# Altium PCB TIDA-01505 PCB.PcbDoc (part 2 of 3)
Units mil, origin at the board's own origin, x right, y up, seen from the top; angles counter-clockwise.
Board outline 7874.02 x 6929.13 mil, 2 copper layers (Top Layer, Bottom Layer), stack 62 mil thick; 307 components, 129 nets, 623 pads, 701 vias.
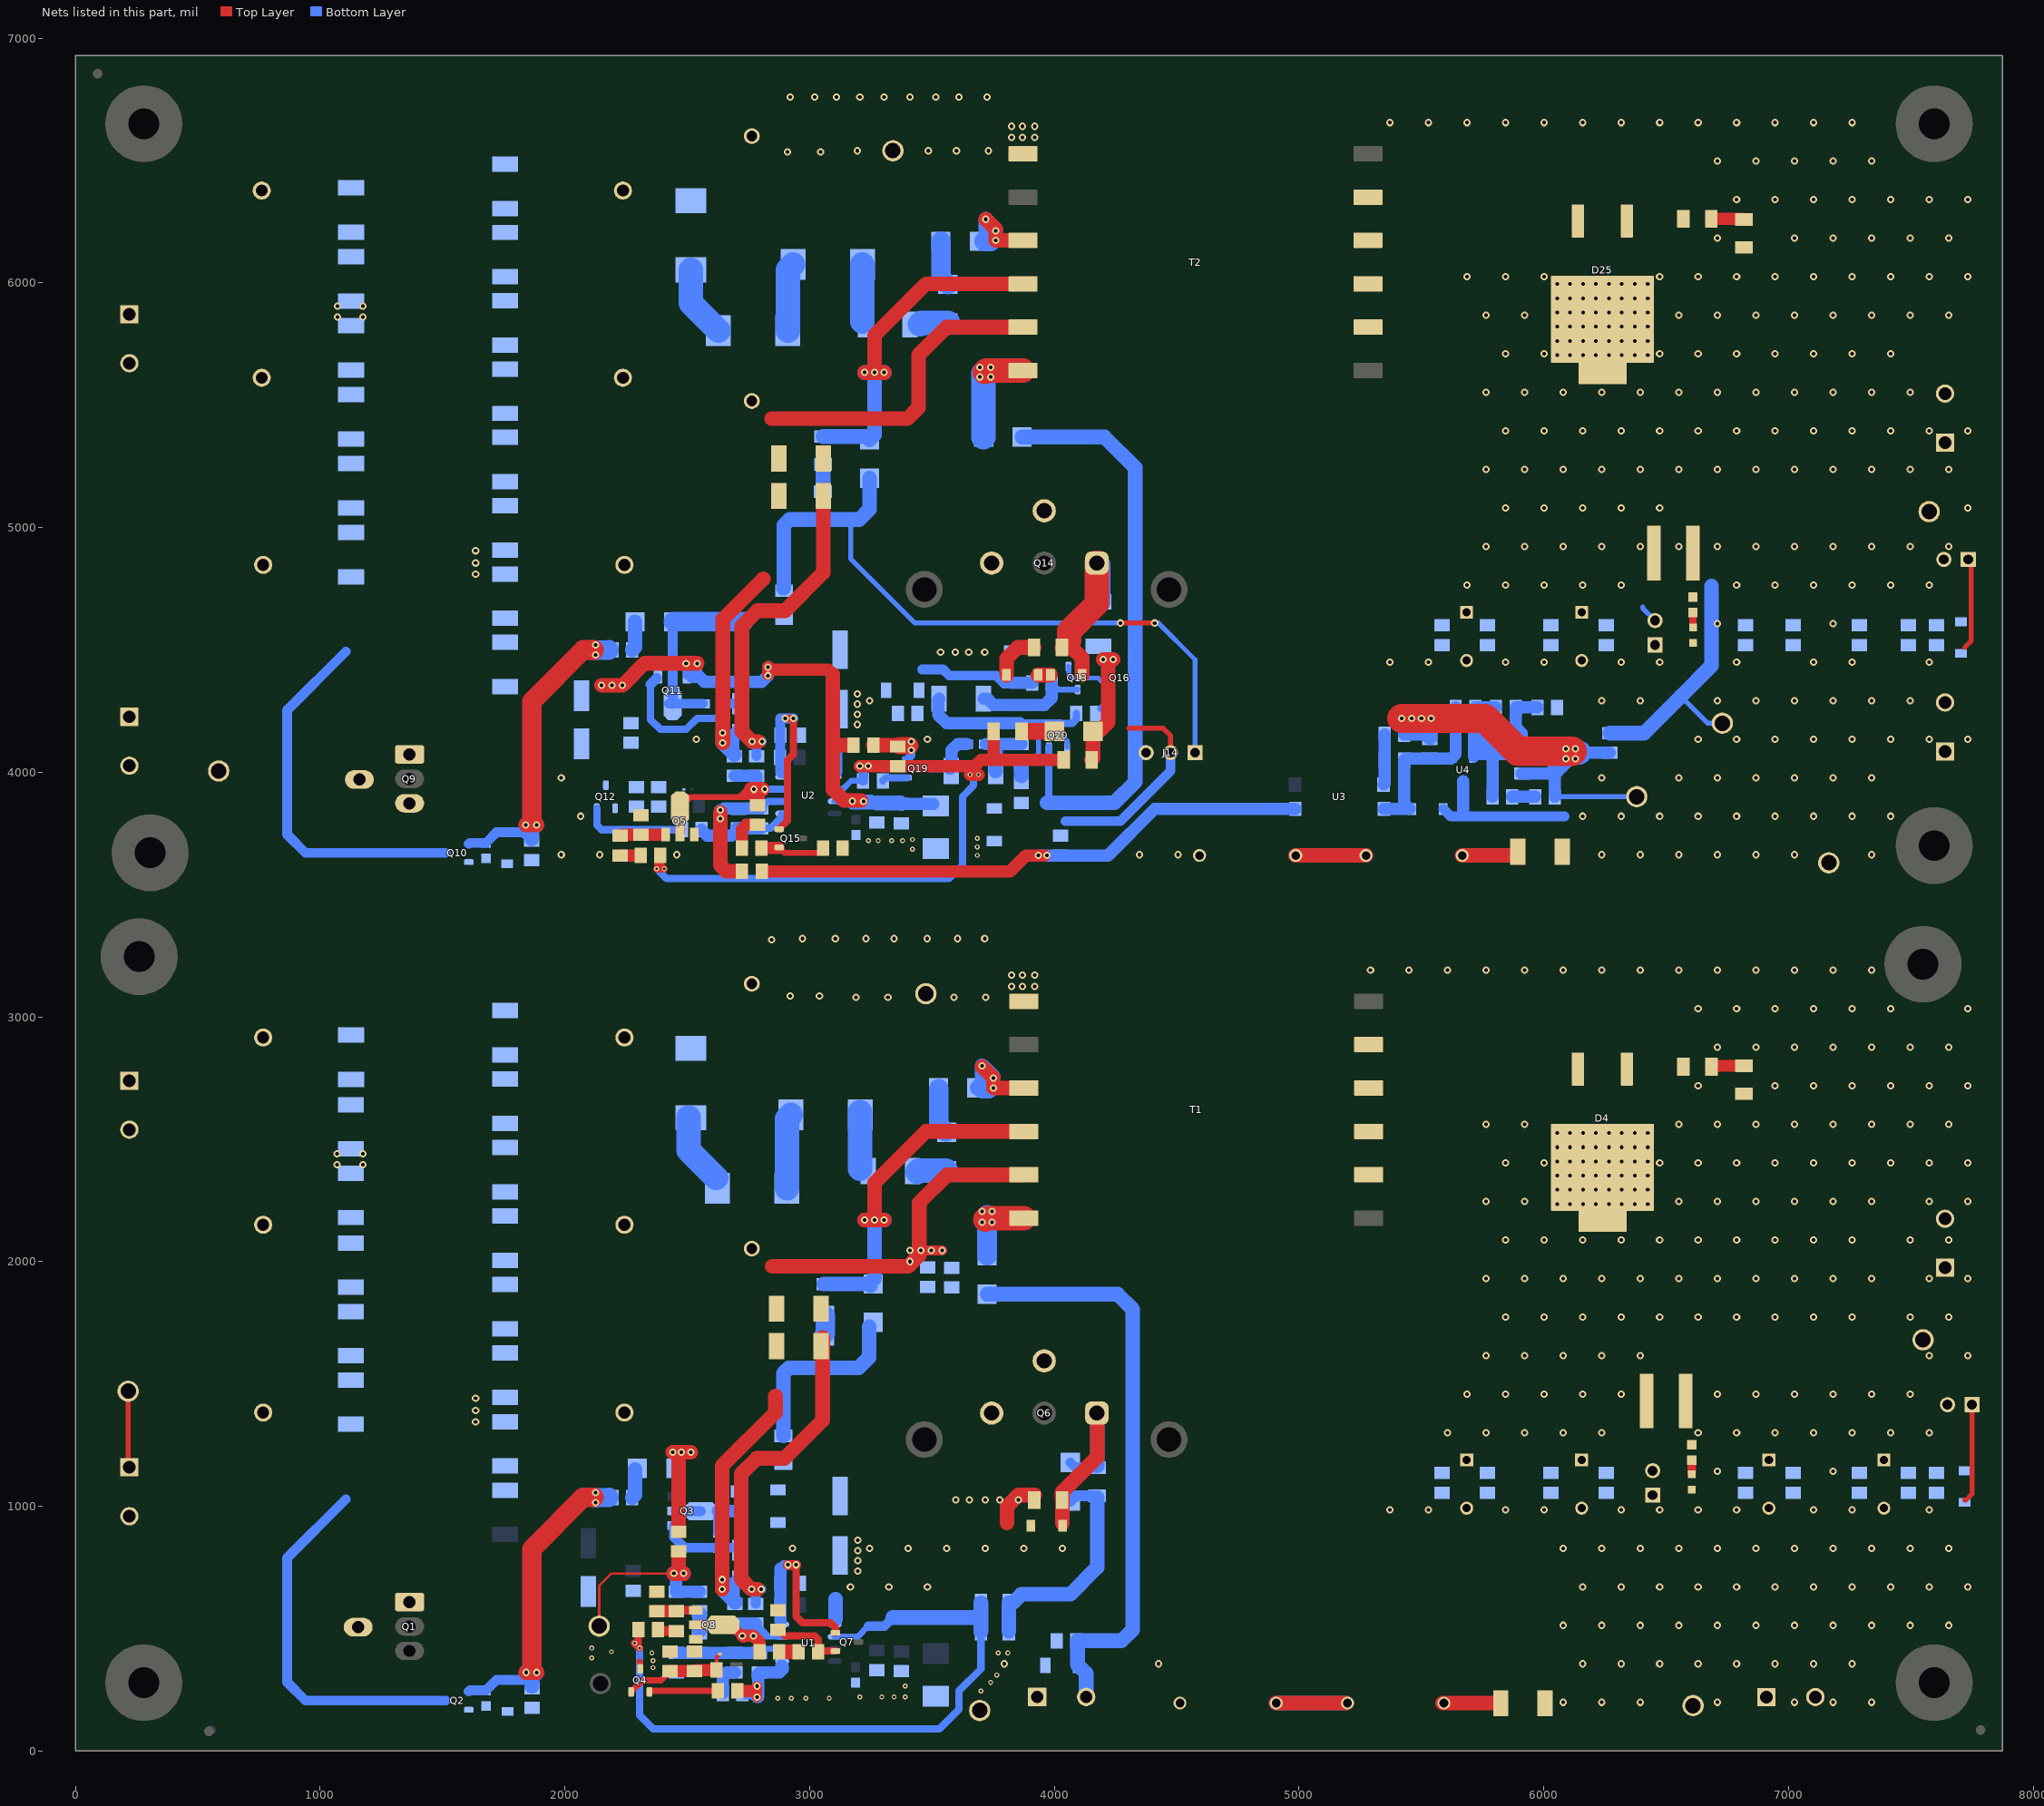
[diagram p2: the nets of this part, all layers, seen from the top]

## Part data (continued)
Q2 Q10: "MOSFET, N-CH, 60 V, 0.17 A, SOT-23", Alternate Manufacturer=None, Manufacturer="Diodes Inc.", Supplier Part Number 1=2N7002-FDICT-ND, Value1="7.5 ohm", Value2="223 nC"
Q3 Q11: library part "PBSS4250X,115, Nexperia", "Transistor, NPN, 50 V, 2 A, SOT-89", Manufacturer=Nexperia, Supplier Part Number 1=568-7297-1-ND, Value1="2 A"
Q4 Q12: library part "MMBT2907ALT1G, ON Semiconductor", "Transistor, PNP, 60 V, 0.6 A, SOT-23", Manufacturer="ON Semiconductor", Supplier Part Number 1=MMBT2907ALT1GOSCT-ND, Value1="0.6 A"
Q5 Q8: library part "DXT2222A-13, Diodes Inc.", "Transistor, NPN, 40 V, 0.6 A, SOT-89", Manufacturer="Diodes Inc.", Supplier Part Number 1=DXT2222ADITR-ND, Value1="0.6 A", Value2=300
Q6 Q14: "MOSFET, N-CH, 1700 V, 5 A, TO-247", Alternate Manufacturer=None, Manufacturer=Cree, Supplier Part Number 1=C2M1000170D-ND, Value1="? ohm", Value2="13 nC"
Q7 Q15: library part "MMBT3904-7-F, Diodes Inc.", "Transistor, NPN, 40 V, 0.2 A, SOT-23", Manufacturer="Diodes Inc.", Supplier Part Number 1=MMBT3904-FDICT-ND, Value1="0.2 A", Value2=400
Q13: library part "BC817-16LT1G, ON Semiconductor", "Transistor, NPN, 45 V, 0.5 A, SOT-23", Manufacturer="ON Semiconductor", Supplier Part Number 1=BC817-16LT1GOSCT-ND, Value1="0.5 A", Value2=250
Q16: library part "BC807-40LT1G, ON Semiconductor", "Transistor, PNP, 45 V, 0.5 A, AEC-Q101, SOT-23", Manufacturer="ON Semiconductor", Supplier Part Number 1=BC807-40LT1GOSCT-ND, Value1="0.5 A", Value2=600
Q19: "MOSFET, P-CH, -50 V, -0.13 A, SOT-23", Alternate Manufacturer=None, Manufacturer="Diodes Inc.", Supplier Part Number 1=BSS84-FDICT-ND, Value1="? ohm", Value2="? nC"
Q20: "MOSFET, N-CH, 60 V, 0.3 A, SOT-23", Alternate Manufacturer=None, Manufacturer=Vishay-Siliconix, Supplier Part Number 1=2N7002K-T1-E3CT-ND, Value1="4 ohm", Value2="0.4 nC"
R1 R36: library part CMP-0016044-2, "RES, 0, 5%, 0.75 W, AEC-Q200 Grade 0, 2010", Manufacturer=Vishay-Dale, Power_W=750mW, Supplier Part Number 1=541-0.0WCT-ND, TempCo=ppm/C, Tolerance_%=5%, Value2=0.75W, Value_Code=0000, ValueDisplayed=0
R2 R4 R6 R9 R14 R15 R37 R39 R41 R44 R48 R49: library part CMP-0077778-1, "RES, 1.5 M, 5%, 0.75 W, AEC-Q200 Grade 0, 2010", Manufacturer=Panasonic, Power_W=750mW, Supplier Part Number 1=P1.5MWCT-ND, Tolerance_%=5%, Value2=0.75W, Value_Code=1M50, ValueDisplayed=1.5M
R3 R5 R7 R8 R10 R11 R38 R40 R42 R43 R45 R46: "RES, 49.9 k, 1%, 0.75 W, AEC-Q200 Grade 0, 2010", Manufacturer=Vishay-Dale, Power_W=0.75, Supplier Part Number 1=541-49.9KACCT-ND, TempCo="100 ppm/C", Tolerance_%=1, Value1=1%, Value2=0.75W, Value_Code=49k9, ValueDisplayed=49.9k
R12 R47: "RES, 33, 5%, 0.75 W, AEC-Q200 Grade 0, 2010", Manufacturer=Vishay-Dale, Power_W=0.75, Supplier Part Number 1=541-33.0WCT-ND, TempCo="200 ppm/C", Tolerance_%=5, Value1=5%, Value2=0.75W, Value_Code=33R0, ValueDisplayed=33
R13 R16 R50 R51: "RES, 1.00 M, 1%, 0.75 W, AEC-Q200 Grade 0, 2010", Manufacturer=Vishay-Dale, Power_W=0.75, Supplier Part Number 1=541-1.0MACCT-ND, TempCo="100 ppm/C", Tolerance_%=1, Value1=1%, Value2=0.75W, Value_Code=1M00, ValueDisplayed=1.00M
R17 R52 R61: "RES, 2.00 k, 1%, 0.125 W, 0805", Manufacturer=Vishay-Dale, Power_W=0.125, Supplier Part Number 1=541-2.00KCCT-ND, TempCo="100 ppm/C", Tolerance_%=1, Value1=1%, Value2=0.125W, Value_Code=2k00, ValueDisplayed=2.00k
R18: "RES, 10.0, 1%, 0.125 W, 0805", Manufacturer=Vishay-Dale, Power_W=0.125, Supplier Part Number 1=541-10.0CCT-ND, TempCo="100 ppm/C", Tolerance_%=1, Value1=1%, Value2=0.125W, Value_Code=10R0, ValueDisplayed=10.0
R19 R54: "RES, 499 k, 1%, 0.1 W, 0603", Manufacturer=Vishay-Dale, Power_W=0.1, Supplier Part Number 1=541-499KHCT-ND, TempCo="100 ppm/C", Tolerance_%=1, Value1=1%, Value2=0.1W, Value_Code=499k
R20 R55: "RES, 4.7 k, 5%, 0.1 W, 0603", Manufacturer=Vishay-Dale, Power_W=0.1, Supplier Part Number 1=541-4.7KGCT-ND, TempCo="200 ppm/C", Tolerance_%=5, Value1=5%, Value2=0.1W, Value_Code=4k70, ValueDisplayed=4.7k
R21 R56: library part CMP-0021998-2, "RES, 10.0 k, 1%, 0.1 W, 0603", Manufacturer=Vishay-Dale, Power_W=100mW, Supplier Part Number 1=541-10.0KHCT-ND, TempCo="100 ppm/C", Tolerance_%=1%, Value2=0.1W, Value_Code=10k0, ValueDisplayed=10.0k
R22 R57: "RES, 20.0 k, 1%, 0.125 W, 0805", Manufacturer=Vishay-Dale, Power_W=0.125, Supplier Part Number 1=541-20.0KCCT-ND, TempCo="100 ppm/C", Tolerance_%=1, Value1=1%, Value2=0.125W, Value_Code=20k0, ValueDisplayed=20.0k
R23 R64: "RES, 49.9, 1%, 0.125 W, 0805", Manufacturer=Vishay-Dale, Power_W=0.125, Supplier Part Number 1=541-49.9CCT-ND, TempCo="100 ppm/C", Tolerance_%=1, Value1=1%, Value2=0.125W, Value_Code=49R9, ValueDisplayed=49.9
R24 R25 R27 R53 R80 R95: "RES, 10.0, 1%, 0.25 W, 1206", Manufacturer=Vishay-Dale, Power_W=0.25, Supplier Part Number 1=541-10.0FCT-ND, TempCo="100 ppm/C", Tolerance_%=1, Value1=1%, Value2=0.25W, Value_Code=10R0, ValueDisplayed=10.0
R26 R60: "RES, 13.0 k, 1%, 0.125 W, 0805", Manufacturer=Vishay-Dale, Power_W=0.125, Supplier Part Number 1=541-13.0KCCT-ND, TempCo="100 ppm/C", Tolerance_%=1, Value1=1%, Value2=0.125W, Value_Code=13k0, ValueDisplayed=13.0k
R28 R30: "RES, 20.5 k, 1%, 0.125 W, 0805", Manufacturer=Vishay-Dale, Power_W=0.125, Supplier Part Number 1=541-20.5KCCT-ND, TempCo="100 ppm/C", Tolerance_%=1, Value1=1%, Value2=0.125W, Value_Code=20k5, ValueDisplayed=20.5k
R29 R66: "RES, 10.0 k, 1%, 0.25 W, 1206", Manufacturer=Vishay-Dale, Power_W=0.25, Supplier Part Number 1=541-10.0KFCT-ND, TempCo="100 ppm/C", Tolerance_%=1, Value1=1%, Value2=0.25W, Value_Code=10k0, ValueDisplayed=10.0k
R31 R32 R67 R68: "RES, 0.91, 1%, 1 W, 2010", Manufacturer=Bourns, Power_W=1, Supplier Part Number 1=652-CRM2010FXR910ELF, TempCo="100 ppm/C", Value1=1%, Value2=1W, Value_Code=R910, ValueDisplayed=0.91
R33 R79 R90 R91: "RES, 100, 1%, 0.25 W, 1206", Manufacturer=Vishay-Dale, Power_W=0.25, Supplier Part Number 1=541-100FCT-ND, TempCo="100 ppm/C", Tolerance_%=1, Value1=1%, Value2=0.25W, Value_Code=100R, ValueDisplayed=100
R34 R71: "RES, 9.09 k, 1%, 0.125 W, 0805", Manufacturer=Vishay-Dale, Power_W=0.125, Supplier Part Number 1=541-9.09KCCT-ND, TempCo="100 ppm/C", Tolerance_%=1, Value1=1%, Value2=0.125W, Value_Code=9k09, ValueDisplayed=9.09k
R35 R72: "RES, 2.2 k, 5%, 0.125 W, 0805", Manufacturer=Vishay-Dale, Power_W=0.125, Supplier Part Number 1=541-2.2KACT-ND, TempCo="200 ppm/C", Tolerance_%=5, Value1=5%, Value2=0.125W, Value_Code=2k20, ValueDisplayed=2.2k
R58 R59 R77 R81: "RES, 0, 5%, 0.125 W, 0805", Manufacturer=Vishay-Dale, Power_W=0.125, Supplier Part Number 1=541-0.0ACT-ND, TempCo="200 ppm/C", Tolerance_%=5, Value1=5%, Value2=0.125W, Value_Code=0000, ValueDisplayed=0
R62: "RES, 1.24 k, 1%, 0.125 W, 0805", Manufacturer=Vishay-Dale, Power_W=0.125, Supplier Part Number 1=541-1.24KCCT-ND, TempCo="100 ppm/C", Tolerance_%=1, Value1=1%, Value2=0.125W, Value_Code=1k24, ValueDisplayed=1.24k
R63 R75 R76 R84: "RES, 1.00 k, 1%, 0.125 W, 0805", Manufacturer=Vishay-Dale, Power_W=0.125, Supplier Part Number 1=541-1.00KCCT-ND, TempCo="100 ppm/C", Tolerance_%=1, Value1=1%, Value2=0.125W, Value_Code=1k00, ValueDisplayed=1.00k
R65: "RES, 10.2 k, 1%, 0.125 W, 0805", Manufacturer=Vishay-Dale, Power_W=0.125, Supplier Part Number 1=541-10.2KCCT-ND, TempCo="100 ppm/C", Tolerance_%=1, Value1=1%, Value2=0.125W, Value_Code=10k2, ValueDisplayed=10.2k
R69: "RES, 12.4 k, 1%, 0.125 W, 0805", Manufacturer=Vishay-Dale, Power_W=0.125, Supplier Part Number 1=541-12.4KCCT-ND, TempCo="100 ppm/C", Tolerance_%=1, Value1=1%, Value2=0.125W, Value_Code=12k4, ValueDisplayed=12.4k
R70: "RES, 6.8 k, 5%, 0.125 W, 0805", Manufacturer=Vishay-Dale, Power_W=0.125, Supplier Part Number 1=541-6.8KACT-ND, TempCo="200 ppm/C", Tolerance_%=5, Value1=5%, Value2=0.125W, Value_Code=6k80, ValueDisplayed=6.8k
R73: "RES, 2.43 k, 1%, 0.125 W, 0805", Manufacturer=Vishay-Dale, Power_W=0.125, Supplier Part Number 1=541-2.43KCCT-ND, TempCo="100 ppm/C", Tolerance_%=1, Value1=1%, Value2=0.125W, Value_Code=2k43, ValueDisplayed=2.43k
R74: "RES, 4.99 k, 1%, 0.125 W, 0805", Manufacturer=Vishay-Dale, Power_W=0.125, Supplier Part Number 1=541-4.99KCCT-ND, TempCo="100 ppm/C", Tolerance_%=1, Value1=1%, Value2=0.125W, Value_Code=4k99, ValueDisplayed=4.99k
R78: "RES, 3.16 k, 1%, 0.125 W, 0805", Manufacturer=Vishay-Dale, Power_W=0.125, Supplier Part Number 1=541-3.16KCCT-ND, TempCo="100 ppm/C", Tolerance_%=1, Value1=1%, Value2=0.125W, Value_Code=3k16, ValueDisplayed=3.16k
R82: "RES, 40.2 k, 1%, 0.125 W, 0805", Manufacturer=Vishay-Dale, Power_W=0.125, Supplier Part Number 1=541-40.2KCCT-ND, TempCo="100 ppm/C", Tolerance_%=1, Value1=1%, Value2=0.125W, Value_Code=40k2, ValueDisplayed=40.2k
R83: "RES, 2.05 k, 1%, 0.125 W, 0805", Manufacturer=Vishay-Dale, Power_W=0.125, Supplier Part Number 1=541-2.05KCCT-ND, TempCo="100 ppm/C", Tolerance_%=1, Value1=1%, Value2=0.125W, Value_Code=2k05, ValueDisplayed=1k
R85 R99: "RES, 374, 1%, 0.125 W, 0805", Manufacturer=Vishay-Dale, Power_W=0.125, Supplier Part Number 1=541-374CCT-ND, TempCo="100 ppm/C", Tolerance_%=1, Value1=1%, Value2=0.125W, Value_Code=374R, ValueDisplayed=374
R86 R92: "RES, 1.50 k, 1%, 0.75 W, AEC-Q200 Grade 0, 2010", Manufacturer=Vishay-Dale, Power_W=0.75, Supplier Part Number 1=541-1.50KACCT-ND, TempCo="100 ppm/C", Tolerance_%=1, Value1=1%, Value2=0.75W, Value_Code=1k50, ValueDisplayed=1.50k
R87: "RES, 3.01 k, 1%, 0.125 W, 0805", Manufacturer=Vishay-Dale, Power_W=0.125, Supplier Part Number 1=541-3.01KCCT-ND, TempCo="100 ppm/C", Tolerance_%=1, Value1=1%, Value2=0.125W, Value_Code=3k01, ValueDisplayed=3.01k
R88: "RES, 100, 1%, 0.125 W, 0805", Manufacturer=Vishay-Dale, Power_W=0.125, Supplier Part Number 1=541-100CCT-ND, TempCo="100 ppm/C", Tolerance_%=1, Value1=1%, Value2=0.125W, Value_Code=100R, ValueDisplayed=100
R89: "RES, 2.00, 1%, 0.75 W, AEC-Q200 Grade 0, 2010", Manufacturer=Vishay-Dale, Power_W=0.75, Supplier Part Number 1=541-2.00ACCT-ND, TempCo="100 ppm/C", Tolerance_%=1, Value1=1%, Value2=0.75W, Value_Code=2R00, ValueDisplayed=2.00
R93 R100: "RES, 37.4, 1%, 0.125 W, 0805", Manufacturer=Vishay-Dale, Power_W=0.125, Supplier Part Number 1=541-37.4CCT-ND, TempCo="100 ppm/C", Tolerance_%=1, Value1=1%, Value2=0.125W, Value_Code=37R4, ValueDisplayed=37.4
R94: "RES, 499, 1%, 0.125 W, 0805", Manufacturer=Vishay-Dale, Power_W=0.125, Supplier Part Number 1=541-499CCT-ND, TempCo="100 ppm/C", Tolerance_%=1, Value1=1%, Value2=0.125W, Value_Code=499R, ValueDisplayed=499
R96: "RES, 237, 1%, 0.125 W, 0805", Manufacturer=Vishay-Dale, Power_W=0.125, Supplier Part Number 1=541-237CCT-ND, TempCo="100 ppm/C", Tolerance_%=1, Value1=1%, Value2=0.125W, Value_Code=237R, ValueDisplayed=237
R97: "RES, 470, 1%, 0.125 W, 0805", Manufacturer=Vishay-Dale, Power_W=0.125, Supplier Part Number 1=541-470CCT-ND, TempCo="100 ppm/C", Tolerance_%=1, Value1=1%, Value2=0.125W, Value_Code=470R, ValueDisplayed=470
R98: "RES, 4.7, 5%, 0.25 W, 1206", Manufacturer=Vishay-Dale, Power_W=0.25, Supplier Part Number 1=541-4.7ECT-ND, TempCo="200 ppm/C", Tolerance_%=5, Value1=5%, Value2=0.25W, Value_Code=4R70, ValueDisplayed=4.7
T1 T2: library part CMP-0077115-3, "Transformer, 1500 uH, SMT", Manufacturer=Coilcraft, ValueDisplayed=1.5mH
TP1 TP3 TP4 TP9 TP11 TP14: "Test Point, Compact, Red, TH", Color=Red, Manufacturer=Keystone, Supplier Part Number 1=36-5005-ND
TP2 TP6 TP10 TP15: "Test Point, Compact, Blue, TH", Color=Blue, Manufacturer=Keystone, Supplier Part Number 1=36-5122-ND
TP7 TP8 TP16: "Test Point, Compact, Black, TH", Color=Black, Manufacturer=Keystone, Supplier Part Number 1=36-5006-ND
U1 U2: library part CMP-0074855-1, "Automotive Catalog BiCMOS Low-Power Current Mode PWM Controller, D0008A (SOIC-8)", Alternate Manufacturer="Texas Instruments"
U3: library part CMP-0006181-2, "Optocoupler, 5 kV, 80-160% CTR, SMT", Manufacturer="Fairchild Semiconductor", Supplier Part Number 1=FOD817ASDCT-ND, Voltage_Isolation_Vrms=5kV
U4: library part CMP-0033164-1, "Automotive Catalog Adjustable Precision Shunt Regulator, 34 ppm / degC, 100 mA, -40 to 125 degC, 3-pin SOT-23 (DBZ), Green (RoHS & no Sb/Br)", Manufacturer="Texas Instruments", Rating=Automotive, Temp Coeff(Typ)(ppm/ degree C)=34
ZZ1: library part AssemblyNoteLabel, Alternate Manufacturer=-
ZZ2 ZZ3 ZZ4: library part AssemblyNote, Alternate Manufacturer=-

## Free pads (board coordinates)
  oval 118.11x76.14 hole 50: 1(1154.96,505.39) 1(1160,3970)
  round 95 / inner round 74.8 / far side round 96 hole 62: 1(3958.78,1594.09) 1(3958.78,5068.66)

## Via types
v1: diameter 30, hole 15, Top Layer to Bottom Layer, 666 vias
v2: diameter 20, hole 10, Top Layer to Bottom Layer, 35 vias

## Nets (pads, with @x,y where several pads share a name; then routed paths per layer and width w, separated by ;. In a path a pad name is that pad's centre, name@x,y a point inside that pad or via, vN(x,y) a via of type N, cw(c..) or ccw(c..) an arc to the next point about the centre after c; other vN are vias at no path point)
+5V_PSR: C34.1 C78.1 C80.1 C81.1 D16.1 J13.2 | length 2418.1
  Bottom Layer w60: D16.1@3725,1866.26 4258.74,1866.26 4320,1805 4320,495 4275,450 4095,450 4095,351.93 C80.1@4096.93,350 4130,316.93 J13.2@4130,220.43
+15Vout: C49.1 C50.1 C57.1 C58.1 C59.1 D27.1 J8.2 J11.1 J11.2 L2.1 R56.2 R64.2 TP11.1 TP14.1 | length 1069.5
  Bottom Layer w20: 6560,4310 6670,4200 TP14.1@6730,4200
  Bottom Layer w60: R64.2@6270,4160 6410,4160 6560,4310 6685,4435 6685,4760
  other v1: 6709.57,4607.73 7182.02,4607.73 6788.31,4765.21 6945.79,4765.21 7103.27,4765.21 7260.76,4765.21 7418.24,4765.21 7575.72,4765.21 6552.09,4922.69 6709.57,4922.69 6867.05,4922.69 7024.53,4922.69 7182.02,4922.69 7339.5,4922.69 7496.98,4922.69 7654.46,4922.69 7733.2,5080.17 7496.98,5237.65 7654.46,5237.65 7575.72,5395.13 7733.2,5395.13 7496.98,5552.61
+15Vout_PSR: C8.1 C9.1 C15.1 C16.1 C24.1 C25.1 C26.1 D11.1 J4.1 J4.2 J5.2 L1.1 R21.2 TP3.1
  other v1: 6709.57,1143.17 7182.02,1143.17 6630.83,1300.65 6788.31,1300.65 6945.79,1300.65 7103.27,1300.65 7260.76,1300.65 7418.24,1300.65 7575.72,1300.65 6709.57,1458.13 6867.05,1458.13 7024.53,1458.13 7182.02,1458.13 7339.5,1458.13 7496.98,1458.13 7575.72,1615.61 7733.2,1615.61 7496.98,1773.09 7654.46,1773.09 7575.72,1930.57 7733.2,1930.57 7496.98,2088.05 7654.46,2088.05 7575.72,2245.53 7733.2,2245.53
+20V: D23.1 J14.1 R80.2 R91.1 | length 2881
  Top Layer w20: v1(4270,4610) v1(4410,4610)
  Bottom Layer w20: 3167.28,5032.87 3167.28,4872.72 3430,4610 v1(4270,4610) ; v1(4410,4610) 4425,4610 4575,4460 J14.1@4575,4080
  Bottom Layer w60: R80.2@2892.56,4752.05 2895,4754.49 2895,5010 2917.87,5032.87 R91.1@3053.78,5032.87 3167.28,5032.87 3202.87,5032.87 3245,5075 D23.1@3245,5201.26
+20V_PSR: C21.1 C73.1 D9.2 R18.2 R53.1 R76.2 | length 394.1
  Top Layer w60: v1(2440,1220) v1(2475,1220) ; R76.2@2465,905 2465,1210 v1(2475,1220) ; v1(2515,1220) v1(2475,1220)
-5V: C69.1 D33.2 J14.3 Q16.3 Q20.2 R94.1 | length 2447.6
  Bottom Layer w30: 3975,3895 3977.6,3897.6 Q20.2@3977.72,4102.76
  Bottom Layer w60: D33.2@3868.19,5370 4205,5370 4330,5245 4330,4080 ; 3970,3875 4245,3875 4330,3960 4330,4080 ; J14.3@4375,4080 4330,4080
COMP: C66.1 R65.2 R81.2 U2.1 | length 397.1
  Bottom Layer w30: C66.1@2800.08,3771.22 2841.22,3771.22 2887.8,3817.8 U2.1@2887.8,3831.22
  Bottom Layer w50: R81.2@2557.56,3764.96 2580,3742.52 2580,3740 2680,3740 R65.2@2710,3770 ; R65.2@2700.08,3771.22 C66.1@2800.08,3771.22
COMP_PSR: C30.1 C32.1 R77.2 U1.1 | length 392.3
  Top Layer w40: v1(2785,220) v1(2785,265)
  Top Layer w50: R77.2@2705,245.43 2779.57,245.43
  Bottom Layer w50: C30.1@2725,235 2770,235 v1(2785,220) ; v1@2790,220 C32.1@2790,300.43 ; C32.1@2790,315.43 C32.1@2795,320.43 2877.05,320.43 2890,333.39 2890,345 2885,350
CS: C70.1 Q5.2 Q5.4 R71.2 R72.1 U2.3 | length 949.9
  Top Layer w25: Q5.4@2470,3855.43 2513.1,3898.54 2713.54,3898.54 ; 2713.54,3898.54 2730,3915 ; 2713.54,3898.54 2771.13,3898.54 2787.56,3914.96 ; 2730,3915 2740,3925 2777.52,3925 2787.56,3914.96 ; 2730,3915 2730.04,3914.96 2787.56,3914.96
  Top Layer w40: Q5.2@2470,3753.07 Q5.4@2470,3855.43
  Top Layer w60: v1@2761.46,3930 v1@2805,3930 ; v1(2772.56,3929.96) v1@2777.52,3925 ; R71.2@2787.56,3870 2787.56,3914.96
  Bottom Layer w30: v1(2772.56,3929.96) 2773.82,3931.22 U2.3@2887.8,3931.22
  Bottom Layer w50: C70.1@2692.56,3984.96 R72.1@2782.56,3984.96 2782.56,3939.96 v1@2773.82,3931.22
  other v1: 2816.1,3929.96
CS_PSR: C35.1 Q8.2 Q8.4 R34.2 R35.1 U1.3 | length 805
  Top Layer w40: Q8.2@2543.07,515 Q8.4@2645.43,515 2680,515 v1(2725,470)
  Top Layer w50: v1@2728.35,466.65 v1(2725,470) v1(2770,470) 2795,445 R34.2@2795,405
  Bottom Layer w25: R35.1@2780,520.43 2810.22,490.22 ; U1.3@2887.72,466.65 2833.78,466.65 ; 2810.22,490.22 2833.78,466.65 ; 2810.22,490.22 2790.22,490.22 v1(2770,470) 2773.35,466.65 2833.78,466.65
  Bottom Layer w50: C35.1@2695,520.43 C35.1@2723.54,520.43 ; C35.1@2723.54,520.43 2725,518.98 v1(2725,470) v1(2770,470) 2770,510.43 R35.1@2780,520.43 C35.1@2723.54,520.43
CS_Rs: Q14.3 R67.2 R68.2 R72.2 | length 1383.4
  Top Layer w60: v1@2790,4125 v1(2765,4125) 2723.03,4166.97 2723.03,4596.97 2786.07,4660 2900,4660 3055.55,4815.55 R68.2@3055.55,5154.27
  Bottom Layer w40: R72.2@2782.56,4064.96 2782.56,4107.44 v1(2765,4125) v1(2805,4125)
CS_Rs_PSR: Q6.3 R31.2 R32.2 R35.2 | length 1383.4
  Top Layer w60: v1@2787.44,660.47 v1(2762.44,660.47) 2720.47,702.44 2720.47,1132.44 2783.51,1195.47 2897.44,1195.47 3052.99,1351.02 R31.2@3052.99,1689.74
  Bottom Layer w40: R35.2@2780,600.43 2780,642.91 v1(2762.44,660.47) v1(2802.44,660.47)
FB: C66.2 R65.1 R74.1 U2.2 | length 613.6
  Top Layer w60: v1@2635,3835 2635,3620 2660,3595 R74.1@2718,3595
  Bottom Layer w30: C66.2@2800.08,3851.22 2830.08,3881.22 U2.2@2887.8,3881.22
  Bottom Layer w50: v1@2635,3811.22 v1(2635,3845) ; v1@2635,3836.22 2650,3851.22 2700.08,3851.22 C66.2@2800.08,3851.22
  other v1: 2635,3810
FB_PSR: C32.2 R28.1 R30.1 R78.2 U1.2 | length 440.2
  Bottom Layer w25: C32.2@2795,400.43 2811.22,416.65 U1.2@2887.72,416.65
  Bottom Layer w50: R78.2@2454.41,400 R28.1@2550,400 2694.57,400 R30.1@2695,400.43 C32.2@2795,400.43
Gate_FET: D36.2 Q13.2 Q16.2 R89.1 R95.2 | length 470.3
  Top Layer w60: R95.2@4152.09,4050 4158.11,4056.02 D36.2@4158.11,4167.26 ; D36.2@4185.55,4169.45 4220,4203.9 4220,4450 v1@4231.1,4461.1 ; v1(4200,4461.1) v1@4231.1,4461.1 ; v1(4240,4461.1) v1@4231.1,4461.1
Gate_IC: R85.1 R87.1 R95.1 R96.1 R98.1 U2.6 | length 3217
  Top Layer w30: R85.1@2380,3655 2380,3610 v2(2375,3605) v2(2405,3605) 2390,3620 R85.1@2390,3660
  Top Layer w40: v1(3205,4025) v1(3240,4025) 3285,4025
  Top Layer w50: v1(3205,4025) R87.1@3360,4025 3675,4025 ; v2(3655,3990) 3670,3990 ; v2(3690,3990) 3670,3990 ; R98.1@3752.28,4167.26 3752.28,4052.72 3755,4050 ; R95.1@4037.91,4050 3755,4050 ; 3670,3990 3675,3995 3675,4025 ; 3675,4025 3700,4050 3755,4050
  Bottom Layer w25: U2.6@3102.36,3931.22 3136.22,3931.22 3170,3965 R96.1@3218.78,3965
  Bottom Layer w30: v2(2375,3605) v2(2405,3605) ; 2385,3595 2415,3565 3570,3565 3625,3620 3625,3900 3670,3945 3670,3990 ; v2(3655,3990) 3670,3990 ; v2(3690,3990) 3670,3990
  Bottom Layer w40: R96.1@3218.78,3965 3218.78,4011.22 v1(3205,4025) v1(3240,4025)
Gate_PSR_FET: D14.1 D15.2 Q6.1 R25.2 R29.2 | length 846
  Top Layer w60: D14.1@4033.25,930.43 4033.25,1033.05 4030.87,1035.43 4030.87,1055.87 4175,1200 4175,1379.17 Q6.1@4173.78,1380.39
  Bottom Layer w40: D15.2@4065,1178.74 4083.74,1160 4143.74,1160 4146.65,1157.09 R25.2@4175,1157.09
  Bottom Layer w60: Q6.1@4173.78,1380.39 4175,1379.17 R25.2@4175,1165
Gate_PSR_IC: R24.1 R27.1 R99.1 U1.6 | length 2864.8
  Top Layer w30: v2(2285,440) v2@2300,425 ; R99.1@2300,495 v2@2300,425 ; v2(2305,420) v2@2300,425
  Bottom Layer w25: U1.6@3102.28,466.65 3196.65,466.65 3240,510
  Bottom Layer w30: v2(2285,440) v2(2305,420) 2305,145 2360,90 3530,90 3610,170 3610,245 3699.91,334.91 R24.1@3699.91,487.75
  Bottom Layer w40: 3240,510 3305,510 3340,545
  Bottom Layer w60: 3340,545 3699.91,545 ; R24.1@3699.91,487.75 3699.91,545 ; R27.1@3699.91,605 3699.91,545
HV_DC: C38.1 C39.1 D17.2 J7.1 J7.2 R37.2 R38.2 T2.1 TP9.1
  other v1: 2910,6535 3045,6535 3195,6540 3485,6540 3600,6540 3730,6540 3825,6595 3870,6595 3920,6595 3825,6640 3870,6640 3920,6640 2920,6760 3020,6760 3110,6760 3205,6760 3305,6760 3410,6760 3515,6760 3610,6760 3725,6760
HV_GND: C36.2 C39.2 C42.2 C43.2 C47.2 C53.2 C54.2 C55.2 C56.2 C60.2 C61.1 C62.1 C63.2 C64.2 C65.2 C69.2 C70.2 C76.2 D24.2 D26.2 D32.1 D35.2 J10.1 J10.2 J14.2 Q5.3 Q10.2 Q12.3 R54.1 R63.1 R66.1 R67.1 R68.1 R75.1 R93.1 T2.5 TP10.1 U2.5 | length 3402.8
  Top Layer w20: 4305,4180 4445,4180 4475,4150 J14.2@4475,4080
  Top Layer w60: v1(2645,4120) v1(2645,4160) 2645,4625 2810,4790 ; 2845,5445 3400,5445 3445,5490 3445,5705 3558.98,5818.98 T2.5@3872.13,5818.98 ; D32.1@3804.31,4397.09 3804.31,4464.31 3850,4510 R66.1@3916.69,4510
  Bottom Layer w40: C70.2@2692.56,4064.96 2692.56,4072.44 2692.56,4162.36 D26.2@2710,4179.8 ; 4045,3800 4270,3800 4475,4005 J14.2@4475,4080
  Bottom Layer w60: v1(2645,4160) v1(2645,4120) C70.2@2692.56,4072.44 ; 3100,4000 3103.15,4003.15 3103.15,4085
  other v1: 1985.17,3662.85 2142.65,3662.85 2457.61,3662.85 4347.37,3662.85 4504.85,3662.85 2063.91,3820.33 1985.17,3977.81 2536.35,4135.29 3481.23,4135.29 3195,4195 3195,4236.67 3195,4278.33 3245.01,4292.77 3195,4320 3535,4490 3595,4490 3650,4490 3715,4490
  other v2: 3685,3660 3420,3685 3685,3695 3240,3720 3280,3720 3335,3720 3380,3720 3420,3725 3685,3730
HV_GND_PSR: C1.2 C5.2 C7.2 C12.2 C18.2 C19.2 C20.2 C21.2 C22.1 C23.1 C28.2 C29.2 C31.2 C34.2 C35.2 C73.2 C74.2 C78.2 C80.2 C81.2 D8.2 D10.2 D14.2 D19.2 J3.1 J3.2 J13.1 Q2.2 Q4.3 Q8.3 R19.1 R29.1 R31.1 R32.1 R78.1 R84.1 R100.1 T1.5 TP2.1 TP8.1 U1.5 | length 4450.6
  Top Layer w10: J3.1@215,1164.13 J3.1@220,1159.13
  Top Layer w20: J3.1@215,1164.13 TP2.1@215,1470
  Top Layer w25: 2305,365 2307.85,362.15 Q4.3@2307.85,335.67
  Top Layer w40: 3447.44,2025.47 3448.15,2026.18 3466.97,2045 v1(3497.5,2045) v1(3541.25,2045)
  Top Layer w60: v1(2642.44,660.47) v1(2642.44,700.47) 2642.44,1165.47 2860,1383.03 2860,1450 ; 2847.44,1980.47 3402.44,1980.47 3402.68,1980.71 ; 2848.15,1980.71 3402.68,1980.71 ; 3806.75,932.56 3806.75,999.78 3852.44,1045.47 R29.1@3919.13,1045.47 ; T1.5@3874.57,2354.45 3561.42,2354.45 3447.44,2240.47 3447.44,2025.47 3402.68,1980.71 ; T1.5@3875.28,2354.69 3562.13,2354.69 3448.15,2240.71 3448.15,2026.18 3448.15,2025.71 3403.15,1980.71 3402.68,1980.71
  Bottom Layer w40: C35.2@2695,600.43 2695,607.91 2695,697.83 D10.2@2712.44,715.28
  Bottom Layer w60: v1@2647.44,695.47 2647.44,655.47 C35.2@2695,607.91 ; 3105.59,538.62 3105.59,620.47
  other v1: 3796.19,355.76 4426.11,355.76 3166.27,670.72 3323.75,670.72 3481.23,670.72 3197.44,735.47 3197.44,777.14 3197.44,818.81 2930.05,828.2 3245.01,828.2 3402.49,828.2 3559.97,828.2 3717.45,828.2 3874.93,828.2 4032.41,828.2 3197.44,860.47 3597.44,1025.47 3652.44,1025.47 3717.44,1025.47 3777.44,1025.47 3852.44,1025.47 3410,2000 3410,2045 3453.75,2045
  other v2: 2870,215 2925,215 2985,215 3080,215 3205,220 3295,220 3345,220 3390,220 3700,245 3390,265 3740,280 3765,310 2360,340 2360,369.22 2110,380 2355,400 3770,400 3810,400 2190,405 2110,420
HV_IN_PSR: C3.1 C5.1 D1.2 J1.1 J1.2 R2.2 R3.2 T1.1 TP1.1
  other v1: 3190,3080 3320,3080 3590,3080 3720,3080 2920,3085 3040,3085 3825,3125 3870,3125 3920,3125 3825,3170 3870,3170 3920,3170 2845,3315 2970,3320 3105,3320 3230,3320 3345,3320 3480,3320 3605,3320 3715,3320
Iso_GND: C44.2 C45.2 C46.2 C48.2 C49.2 C50.2 C51.2 C52.2 C57.2 C58.2 C59.2 D27.2 D28.1 D31.2 J8.1 J9.1 J12.1 J12.2 R36.2 R73.1 T2.8 T2.9 TP16.1 U4.3 | length 1002.3
  Top Layer w20: 7720,4510 7747.5,4537.5 7747.5,4857.5 J8.1@7735,4870
  Bottom Layer w40: D31.2@5589.47,3850 5619.47,3820 6085,3820
  Bottom Layer w50: 5670,3845 U4.3@5670,3962.76
  other v1: 6237.13,3662.85 6394.61,3662.85 6552.09,3662.85 6709.57,3662.85 6867.05,3662.85 7024.53,3662.85 7339.5,3662.85 6158.39,3820.33 6315.87,3820.33 6473.35,3820.33 6630.83,3820.33 6788.31,3820.33 6945.79,3820.33 7103.27,3820.33 7260.76,3820.33 7418.24,3820.33 6237.13,3977.81 6552.09,3977.81 6709.57,3977.81 6867.05,3977.81 7024.53,3977.81 7182.02,3977.81 7339.5,3977.81 6630.83,4135.29 6788.31,4135.29 6945.79,4135.29 7103.27,4135.29 7260.76,4135.29 7418.24,4135.29 7575.72,4135.29 7733.2,4135.29 6237.13,4292.77 6394.61,4292.77 6709.57,4292.77 6867.05,4292.77 7024.53,4292.77 7182.02,4292.77 7339.5,4292.77 7496.98,4292.77 5370.99,4450.25 5528.47,4450.25 5843.43,4450.25 6000.91,4450.25 6315.87,4450.25 6473.35,4450.25 6788.31,4450.25 7103.27,4450.25 7260.76,4450.25 7575.72,4450.25
Iso_GND_PSR: C8.2 C9.2 C10.2 C11.2 C13.2 C14.2 C15.2 C16.2 C17.2 C24.2 C25.2 C26.2 C27.2 D11.2 D12.1 J2.1 J5.1 J6.1 J6.2 R1.2 T1.8 T1.9 TP7.1 | length 405.4
  Top Layer w20: 7720,1025 7725,1025 7750,1050 J5.1@7750,1415
  other v1: 6079.65,198.28 6237.13,198.28 6394.61,198.28 6709.57,198.28 7024.53,198.28 7182.02,198.28 7339.5,198.28 6158.39,355.76 6315.87,355.76 6473.35,355.76 6630.83,355.76 6788.31,355.76 6945.79,355.76 7103.27,355.76 7260.76,355.76 6079.65,513.24 6237.13,513.24 6394.61,513.24 6552.09,513.24 6709.57,513.24 6867.05,513.24 7024.53,513.24 7182.02,513.24 7339.5,513.24 7496.98,513.24 7654.46,513.24 6158.39,670.72 6315.87,670.72 6473.35,670.72 6630.83,670.72 6788.31,670.72 6945.79,670.72 7103.27,670.72 7260.76,670.72 7418.24,670.72 7575.72,670.72 7733.2,670.72 6079.65,828.2 6237.13,828.2 6394.61,828.2 6552.09,828.2 6709.57,828.2 6867.05,828.2 7024.53,828.2 7182.02,828.2 7339.5,828.2 7496.98,828.2 7654.46,828.2 5370.99,985.68 5528.47,985.68 5843.43,985.68 6000.91,985.68 6315.87,985.68 6473.35,985.68 6630.83,985.68 6788.31,985.68 7103.27,985.68 7260.76,985.68 7575.72,985.68
NetC1_1: C1.1 C2.2 | length 572.6
  Top Layer w60: C1.1@4906.85,195.43 C2.2@5193.15,195.43
  Bottom Layer w60: C1.1@4906.85,195.43 C2.2@5193.15,195.43
NetC2_1: C2.1 R1.1 | length 212.6
  Top Layer w60: C2.1@5586.85,195.43 R1.1@5799.45,195.43
NetC3_2: C3.2 C6.1 R4.1 R6.2
  other v1: 1068.78,2395.85 1173.78,2395.85 1068.78,2440.85 1173.78,2440.85
NetC4_1: C4.1 D7.2 T1.4 | length 1470.9
  Top Layer w60: v1(3225,2170) v1(3265,2170) ; v1(3305,2170) v1(3265,2170) ; 3476.14,2532.4 3265,2321.26 v1(3265,2170) ; 3479.29,2531.85 T1.4@3875.28,2531.85
  Bottom Layer w60: C4.1@3058.15,1907.76 D7.2@3241.1,1907.76 ; v1(3225,2170) v1(3265,2170) ; D7.2@3248.15,1900.71 D7.2@3241.1,1907.76 ; v1(3305,2170) v1(3265,2170) ; D7.2@3241.1,1907.76 3265,1931.65 v1(3265,2170)
NetC4_2: C4.2 R90.2 | length 73.6
  Bottom Layer w80: 3062.64,1710 3063.78,1711.14 ; R90.2@3063.78,1708 C4.2@3063.78,1780
NetC6_2: C6.2 C7.1 R9.1 R14.2
NetC10_1: C10.1 C11.1 C13.1 C14.1 C17.1 C27.1 C72.1 D4.4 H9.1 J2.2 L1.2
  other v1: 5607.21,1300.65 5764.69,1300.65 5922.17,1300.65 6079.65,1300.65 6237.13,1300.65 5685.95,1458.13 5843.43,1458.13 6000.91,1458.13 6158.39,1458.13 6315.87,1458.13 5764.69,1615.61 5922.17,1615.61 6079.65,1615.61 6237.13,1615.61 6394.61,1615.61 5843.43,1773.09 6000.91,1773.09 6158.39,1773.09 6315.87,1773.09 6473.35,1773.09 6630.83,1773.09 6788.31,1773.09 6945.79,1773.09 7103.27,1773.09 7260.76,1773.09 5764.69,1930.57 5922.17,1930.57 6079.65,1930.57 6237.13,1930.57 6394.61,1930.57 6552.09,1930.57 6709.57,1930.57 6867.05,1930.57 7024.53,1930.57 7182.02,1930.57 7339.5,1930.57 5843.43,2088.05 6000.91,2088.05 6158.39,2088.05 6315.87,2088.05 6473.35,2088.05 6630.83,2088.05 6788.31,2088.05 6945.79,2088.05 7103.27,2088.05 7260.76,2088.05 6055,2235 6107.86,2235 6160.71,2235 6213.57,2235 6266.43,2235 6319.29,2235 6372.14,2235 6425,2235 5764.69,2245.53 5922.17,2245.53 6552.09,2245.53 6709.57,2245.53 6867.05,2245.53 7024.53,2245.53 7182.02,2245.53 7339.5,2245.53 6055,2293.06 6107.86,2293.06 6160.71,2293.06 6213.57,2293.06 6266.43,2293.06 6319.29,2293.06 6372.14,2293.06 6425,2293.06 6055,2351.13 6107.86,2351.13 6160.71,2351.13 6213.57,2351.13 6266.43,2351.13 6319.29,2351.13 6372.14,2351.13 6425,2351.13 5843.43,2403.01 6000.91,2403.01 6473.35,2403.01 6630.83,2403.01 6788.31,2403.01 6945.79,2403.01 7103.27,2403.01 7260.76,2403.01 7418.24,2403.01 7575.72,2403.01 7733.2,2403.01 6055,2409.19 6107.86,2409.19 6160.71,2409.19 6213.57,2409.19 6266.43,2409.19 6319.29,2409.19 6372.14,2409.19 6425,2409.19 6055,2467.25 6107.86,2467.25 6160.71,2467.25 6213.57,2467.25 6266.43,2467.25 6319.29,2467.25 6372.14,2467.25 6425,2467.25 6055,2525.32 6107.86,2525.32 6160.71,2525.32 6213.57,2525.32 6266.43,2525.32 6319.29,2525.32 6372.14,2525.32 6425,2525.32 5764.69,2560.49 5922.17,2560.49 6552.09,2560.49 6709.57,2560.49 6867.05,2560.49 7024.53,2560.49 7182.02,2560.49 7339.5,2560.49 7496.98,2560.49 7654.46,2560.49 6630.83,2717.97 6945.79,2717.97 7103.27,2717.97 7260.76,2717.97 7418.24,2717.97 7575.72,2717.97 7733.2,2717.97 6709.57,2875.45 6867.05,2875.45 7024.53,2875.45 7182.02,2875.45 7339.5,2875.45 7496.98,2875.45 7654.46,2875.45 6630.83,3032.93 6788.31,3032.93 6945.79,3032.93 7103.27,3032.93 7260.76,3032.93 7418.24,3032.93 7733.2,3032.93 5292.25,3190.41 5449.73,3190.41 5607.21,3190.41 5764.69,3190.41 5922.17,3190.41 6079.65,3190.41 6237.13,3190.41 6394.61,3190.41 6552.09,3190.41 6709.57,3190.41 6867.05,3190.41 7024.53,3190.41 7182.02,3190.41 7339.5,3190.41
NetC12_1: C12.1 D8.1 Q2.1 R17.1 R19.2 | length 1309.3
  Top Layer w60: 1865,345.43 1840,320.43 v1(1885,320.43)
  Top Layer w80: 1865,345.43 1865,825.43 2075,1035.43 2119.42,1035.43
  Bottom Layer w40: Q2.1@1607.2,242.8 1611.3,246.89 R19.2@1677.44,246.89 1720.41,289.86 1764.22,289.86 1829.26,289.86
  Bottom Layer w60: v1@1840,320.43 v1(1885,320.43) ; C12.1@1865,263.47 1865,299.2 v1@1886.27,320.47
  Bottom Layer w80: 2124.81,1034.9 2125.2,1034.9 R17.1@2180,1035.43
  other v1: 1841.27,320.47 2125,1015.43 2125,1055.43
NetC22_2: C22.2 C23.2 D13.2 Q4.1 R22.2 | length 457.1
  Top Layer w15: R22.2@2620,330.43 2620,381.97 D13.2@2633.46,395.43
  Top Layer w25: Q4.1@2270.45,241.18 2317.69,288.43 2393,288.43 C23.2@2430,325.43
  Top Layer w50: C23.2@2430,325.43 C22.2@2530,325.43 2535,330.43 R22.2@2620,330.43
NetC30_2: C30.2 R30.2 | length 126.4
  Bottom Layer w50: C30.2@2645,235 2645,305 2660.43,320.43 R30.2@2695,320.43
NetC33_1: C33.1 Q7.2 R84.2 | length 293.9
  Top Layer w30: R84.2@2875,495 2900,470 3020,470 3035,455 C33.1@3035,405.43 ; C33.1@3037.56,407.99 Q7.2@3105.31,407.99
NetC33_2: C33.2 R34.1 | length 65
  Top Layer w60: R34.1@2880,405 C33.2@2945,405
NetC36_1: C36.1 C37.2 | length 572.6
  Top Layer w60: C36.1@4986.85,3660 C37.2@5273.15,3660
  Bottom Layer w60: C36.1@4986.85,3660 C37.2@5273.15,3660
NetC37_1: C37.1 R36.1 | length 233.8
  Top Layer w60: C37.1@5666.85,3660 5879.45,3660 R36.1@5894.45,3675
NetC38_2: C38.2 C41.1 R39.1 R41.2
  other v1: 1070,5860 1175,5860 1070,5905 1175,5905
NetC40_1: C40.1 D23.2 T2.4 | length 1482
  Top Layer w60: v1(3225,5633.74) v1(3265,5633.74) ; v1(3305,5633.74) v1(3265,5633.74) ; T2.4@3872.13,5996.14 3476.14,5996.14 3265,5785 v1(3265,5633.74)
  Bottom Layer w60: C40.1@3055,5372.05 3237.95,5372.05 D23.2@3245,5365 ; v1(3225,5633.74) v1(3265,5633.74) ; D23.2@3245,5358.74 3265,5378.74 v1(3265,5633.74) ; v1(3305,5633.74) v1(3265,5633.74)
NetC40_2: C40.2 R91.2 | length 111.3
  Bottom Layer w60: R91.2@3053.78,5147.05 3055,5148.27 C40.2@3055,5257.87
NetC41_2: C41.2 C47.1 R44.1 R48.2
NetC42_1: C42.1 C43.1 C60.1 C76.1 D34.2 Q11.2 Q11.4 R55.2 R58.2 R80.1 | length 1235.1
  Bottom Layer w40: Q11.4@2425.43,4280 Q11.4@2440,4280 ; D34.2@2443.74,4615 2440,4611.26 Q11.2@2440,4381.93 Q11.4@2440,4280 ; R55.2@2563.5,4280 Q11.4@2440.43,4280 ; 3460,4420 3545,4420 3570,4395 3762.6,4395 3794.53,4363.07 C60.1@3825,4363.07 C60.1@3826.93,4365 ; Q11.4@2440,4280 Q11.4@2440.43,4280 ; Q11.4@2440,4280 Q11.4@2440,4279.57 Q11.4@2440.43,4280
  Bottom Layer w50: C60.1@3826.93,4365 R58.2@3908.78,4365
  Bottom Layer w80: D34.2@2443.74,4615 2730,4615
NetC44_1: C44.1 C45.1 C46.1 C48.1 C51.1 C52.1 C75.1 D25.4 H10.1 J9.2 L2.2 | length 76.1
  Bottom Layer w20: 6404,4675 6404,4671 J9.2@6455,4620
  other v1: 5685.95,4765.21 5843.43,4765.21 6000.91,4765.21 6158.39,4765.21 6315.87,4765.21 5764.69,4922.69 5922.17,4922.69 6079.65,4922.69 6237.13,4922.69 6394.61,4922.69 5843.43,5080.17 6000.91,5080.17 6158.39,5080.17 6315.87,5080.17 6473.35,5080.17 5764.69,5237.65 5922.17,5237.65 6079.65,5237.65 6237.13,5237.65 6394.61,5237.65 6552.09,5237.65 6709.57,5237.65 6867.05,5237.65 7024.53,5237.65 7182.02,5237.65 7339.5,5237.65 5843.43,5395.13 6000.91,5395.13 6158.39,5395.13 6315.87,5395.13 6473.35,5395.13 6630.83,5395.13 6788.31,5395.13 6945.79,5395.13 7103.27,5395.13 7260.76,5395.13 7418.24,5395.13 5764.69,5552.61 5922.17,5552.61 6079.65,5552.61 6237.13,5552.61 6394.61,5552.61 6552.09,5552.61 6709.57,5552.61 6867.05,5552.61 7024.53,5552.61 7182.02,5552.61 7339.5,5552.61 6055,5705 6107.86,5705 6160.71,5705 6213.57,5705 6266.43,5705 6319.29,5705 6372.14,5705 6425,5705 5843.43,5710.09 6000.91,5710.09 6473.35,5710.09 6630.83,5710.09 6788.31,5710.09 6945.79,5710.09 7103.27,5710.09 7260.76,5710.09 7418.24,5710.09 6055,5763.06 6107.86,5763.06 6160.71,5763.06 6213.57,5763.06 6266.43,5763.06 6319.29,5763.06 6372.14,5763.06 6425,5763.06 6055,5821.13 6107.86,5821.13 6160.71,5821.13 6213.57,5821.13 6266.43,5821.13 6319.29,5821.13 6372.14,5821.13 6425,5821.13 5764.69,5867.57 5922.17,5867.57 6552.09,5867.57 6709.57,5867.57 6867.05,5867.57 7024.53,5867.57 7182.02,5867.57 7339.5,5867.57 7496.98,5867.57 7654.46,5867.57 6055,5879.19 6107.86,5879.19 6160.71,5879.19 6213.57,5879.19 6266.43,5879.19 6319.29,5879.19 6372.14,5879.19 6425,5879.19 6055,5937.25 6107.86,5937.25 6160.71,5937.25 6213.57,5937.25 6266.43,5937.25 6319.29,5937.25 6372.14,5937.25 6425,5937.25 6055,5995.31 6107.86,5995.31 6160.71,5995.31 6213.57,5995.31 6266.43,5995.31 6319.29,5995.31 6372.14,5995.31 6425,5995.31 5685.95,6025.05 5843.43,6025.05 6000.91,6025.05 6473.35,6025.05 6630.83,6025.05 6788.31,6025.05 6945.79,6025.05 7103.27,6025.05 7260.76,6025.05 7418.24,6025.05 7575.72,6025.05 7733.2,6025.05 6709.57,6182.53 7024.53,6182.53 7182.02,6182.53 7339.5,6182.53 7496.98,6182.53 7654.46,6182.53 6788.31,6340.02 6945.79,6340.02 7103.27,6340.02 7260.76,6340.02 7418.24,6340.02 7575.72,6340.02 7733.2,6340.02 6709.57,6497.5 6867.05,6497.5 7024.53,6497.5 7182.02,6497.5 7339.5,6497.5 5370.99,6654.98 5528.47,6654.98 5685.95,6654.98 5843.43,6654.98 6000.91,6654.98 6158.39,6654.98 6315.87,6654.98 6473.35,6654.98 6630.83,6654.98 6788.31,6654.98 6945.79,6654.98 7103.27,6654.98 7260.76,6654.98
NetC53_1: C53.1 D24.1 Q10.1 R52.1 R54.2 | length 1373.1
  Top Layer w60: 1865,3810 v1(1840,3785) v1(1885,3785)
  Top Layer w80: 1865,3810 1865,4290 2075,4500 2119.42,4500
  Bottom Layer w40: Q10.1@1607.2,3707.36 1611.3,3711.46 R54.2@1677.44,3711.46 1720.41,3754.43 D24.1@1764.22,3754.43 1829.26,3754.43 C53.1@1863.73,3719.96
  Bottom Layer w60: v1(1840,3785) v1(1885,3785) 1863.73,3763.73 C53.1@1863.73,3728
  Bottom Layer w80: 2110,4500 2110.67,4499.33 2124.81,4499.47 2125.2,4499.47 R52.1@2180,4500
  other v1: 2125,4480 2125,4520
NetC61_2: C61.2 C62.2 D29.2 Q12.1 R57.2
NetC67_1: C67.1 Q15.2 R63.2 | length 267.5
  Top Layer w25: Q15.2@2875.31,3692.56 2897.87,3670 3035,3670 R63.2@3055,3690
  Top Layer w50: C67.1@2802.56,3689.96 Q15.2@2872.72,3689.96
NetC67_2: C67.2 R71.1 | length 149.8
  Top Layer w50: C67.2@2722.56,3689.96 2722.56,3767.48 2740.08,3785 2787.52,3785 R71.1@2787.56,3784.96
NetC68_1: C68.1 C71.1 R69.1 R73.2 R82.1 U4.2 | length 1237.6
  Bottom Layer w50: R82.1@5790.32,3899.37 5790.32,4055.32 5810,4075 ; 5810.63,4074.37 5810,4075 ; 5885,4185 C68.1@5885,4265 R73.2@5975,4265 ; R69.1@5915,4080 R69.1@5910,4075 ; C71.1@5715,4124.37 5715,4164.37 5805,4164.37 5810,4169.37 ; C71.1@5715,4124.37 5715,4064.84 5725.16,4075 5810,4075 ; C71.1@5715,4124.37 5717.18,4122.19 5810,4122.19 ; 5810,4075 R69.1@5910,4075 ; 5810,4075 5810,4122.19 ; 5810,4122.19 5907.81,4122.19 5910,4120 ; 5810,4122.19 5810,4169.37 ; 5810,4169.37 5900.63,4169.37 5910,4160 5910,4120 ; R69.1@5910,4075 5910,4120
NetC68_2: C68.2 R70.2 | length 85
  Bottom Layer w50: R70.2@5720,4265 C68.2@5805,4265
NetC71_2: C71.2 D31.1 R62.1 R70.1 R83.1 U3.2 U4.1 | length 724.9
  Bottom Layer w50: U3.2@5346.59,3850 5452,3850 5430,3872 R83.1@5430,4050 5435,4055 R62.1@5535,4055 5620,4055 5640,4075 5640,4150 R70.1@5640,4265
NetC72_2: C72.2 R33.2 | length 133.9
  Top Layer w50: R33.2@6685.09,2796.43 6688.61,2799.96 C72.2@6817.52,2799.96
NetC74_1: C74.1 R23.2 R76.1 TP4.1 | length 827.3
  Top Layer w10: TP4.1@2140,510 2140,675 2190,725 v1(2445,725)
  Top Layer w60: v1(2445,725) 2460,725 ; R76.1@2465,805 2465,730 2460,725 ; v1(2485,725) 2460,725
  Bottom Layer w10: C74.1@2454.41,650 C74.1@2454.41,650
  Bottom Layer w50: v1(2445,725) 2454.41,715.59 C74.1@2454.41,650 R23.2@2550,650
  Bottom Layer w60: v1(2445,725) v1(2485,725)
NetC75_2: C75.2 R79.2 | length 130.8
  Top Layer w50: R79.2@6684.61,6262.44 C75.2@6815.43,6262.44
NetC77_1: C77.1 R61.2 R62.2 R64.1 R69.2 TP15.1 | length 2082.3
  Top Layer w120: v1(5420,4220) v1(5460,4220) v1(5500,4220) v1(5540,4220) 5760,4220 5895,4085 6115,4085
  Bottom Layer w20: C77.1@6045.31,3899.37 6045.94,3900 TP15.1@6380,3900
  Bottom Layer w50: 5445,4190 5525,4190 5530,4185 R62.2@5530,4140 ; R69.2@5910,3995 6026.14,3995 6045.31,3975.83 ; C77.1@6045.31,3899.37 6045.31,3975.83 ; 6045.31,4005.31 6045.31,3975.83 ; 6195,4080 R64.1@6270,4080 ; R62.2@5530,4140 R62.2@5535,4135 5540,4140 v1(5540,4220) v1(5500,4220) v1(5460,4220) v1(5420,4220) 5430,4210 R61.2@5430,4155 5515,4155 R62.2@5530,4140
  Bottom Layer w70: 6045.31,4005.31 6120,4080
  Bottom Layer w100: 6100,4080 6145,4080
  other v1: 6090,4055 6130,4055 6090,4095 6130,4095
NetC77_2: C77.2 R82.2 | length 95
  Bottom Layer w50: R82.2@5870.32,3899.37 C77.2@5965.31,3899.37
NetC79_1: C79.1 Q19.3 R92.2 | length 244.6
  Bottom Layer w30: Q19.3@3492.24,4015 3569.45,4015 R92.2@3579.45,4005
  Bottom Layer w50: R92.2@3569.45,4015 3580,4025.55 3580,4090 3605,4115 C79.1@3643.5,4115
NetC79_2: C79.2 R92.1 R97.1 | length 225.2
  Bottom Layer w50: C79.2@3720,4115 R97.1@3865,4115
  Bottom Layer w60: 3760,4085 3760.55,4084.45 R92.1@3760.55,4005
NetC82_1: C82.1 R85.2 | length 85
  Top Layer w50: C82.1@2225,3660 R85.2@2310,3660
NetC82_2: C82.2 Q5.1 R93.2 | length 167.1
  Top Layer w50: C82.2@2225,3740 2230,3745 R93.2@2310,3745 2390,3745
NetC83_1: C83.1 R99.2 | length 77.1
  Top Layer w40: R99.2@2380,495 2385,490 C83.1@2455,490
NetC83_2: C83.2 Q8.1 R100.2 | length 161.9
  Top Layer w35: C83.2@2455,570 2459.05,574.06 Q8.1@2535.2,574.06
  Top Layer w50: R100.2@2375,570 C83.2@2455,570
NetD1_1: D1.1 D2.2 | length 295.2
  Bottom Layer w100: D1.1@2504.96,2589.57 2504.96,2454.57 D2.2@2618.23,2341.3
NetD2_1: D2.1 D3.2 | length 306.8
  Bottom Layer w100: D2.1@2906.73,2300 2906.73,2583.46 D3.2@2923.27,2600
NetD3_1: D3.1 R12.1 | length 232.3
  Bottom Layer w100: 3206.69,2379.02 D3.1@3206.69,2611.3
NetD4_1: D4.1 D4.3 R33.1 T1.10 T1.11
NetD5_1: D5.1 R12.2 | length 117.6
  Bottom Layer w100: R12.2@3441.22,2366.34 3447.48,2372.6 D5.1@3556.22,2372.6
NetD5_2: D5.2 D6.1 | length 188.2
  Bottom Layer w80: D6.1@3527.48,2706.34 3527.48,2558.82 D5.2@3556.22,2530.08
NetD7_1: D7.1 R53.2 R90.1 | length 758.7
  Bottom Layer w60: R53.2@2892.56,1287.48 2892.56,1542.99 2915.43,1565.87 3051.34,1565.87 3200.43,1565.87 3242.56,1607.99 D7.1@3242.56,1734.25
NetD9_1: D9.1 R17.2 | length 120.3
  Bottom Layer w60: R17.2@2275.08,1034.76 2286.26,1045.94 D9.1@2286.26,1150.43
NetD10_1: D10.1 Q3.1 R20.1 | length 334.4
  Bottom Layer w40: Q3.1@2445.2,920.94 2445.2,873.35 2488.54,830 2700.2,830 D10.1@2710,820.2
NetD12_2: D12.2 R21.1 | length 57
  Top Layer w35: D12.2@6605,1131.5 R21.1@6605,1188.5
NetD15_1: D15.1 R24.2 R25.1 R27.2 | length 945.1
  Bottom Layer w30: R25.1@4172.91,1045 R25.1@4175,1042.91
  Bottom Layer w45: D15.1@4065,1021.26 4086.65,1042.91 R25.1@4175,1042.91
  Bottom Layer w60: R24.2@3814.09,487.75 R27.2@3814.09,605 3830,605 3865,640 4065,640 4175,750 R25.1@4175,1035
NetD16_2: D16.2 T1.6 | length 325.7
  Top Layer w100: 3718.5,2171.06 3724.96,2177.52 T1.6@3875.28,2177.52
  Bottom Layer w80: D16.2@3725,2023.74 3725,2190
  other v1: 3705,2160 3745,2160 3705,2205 3745,2205
NetD17_1: D17.1 D18.2 | length 295.2
  Bottom Layer w100: D17.1@2513.74,6053.23 2513.74,5918.23 D18.2@2627.01,5804.96
NetD18_1: D18.1 D20.2 | length 278.9
  Bottom Layer w100: D18.1@2910.47,5804.96 2910.47,6053.43 D20.2@2932.01,6074.96
NetD20_1: D20.1 R47.1 | length 232.3
  Bottom Layer w100: R47.1@3215.47,5842.68 D20.1@3215.47,6074.96
NetD21_1: D21.1 R47.2 | length 117.6
  Bottom Layer w100: 3450,5830 3456.26,5836.26 D21.1@3565,5836.26
NetD21_2: D21.2 D22.1 | length 188.2
  Bottom Layer w80: D22.1@3536.26,6170 3536.26,6022.48 D21.2@3565,5993.74
NetD25_1: D25.1 D25.3 R79.1 T2.10 T2.11
NetD26_1: D26.1 Q11.1 R55.1 | length 617.3
  Bottom Layer w30: 2350,4358.86 2350,4215 2390,4175 2495,4175 2540,4220 2618.2,4220 2641.5,4243.29 R55.1@2641.5,4280
  Bottom Layer w40: 2350,4358.86 Q11.1@2375,4385 ; R55.1@2645.83,4280.2 D26.1@2710,4280.2
NetD28_2: D28.2 R56.1 | length 62
  Top Layer w30: D28.2@6610,4591.5 R56.1@6610,4653.5
NetD30_1: D30.1 Q14.1 R66.2 R89.2 | length 694.9
  Top Layer w60: R66.2@4030.87,4510 4070,4510 4113.25,4466.75 D30.1@4113.25,4397.09
  Top Layer w100: 4060,4539.13 4060,4575 4173.78,4688.78 Q14.1@4173.78,4854.96
  Bottom Layer w100: Q14.1@4173.78,4854.96 4180,4848.74 R89.2@4180,4695.55
NetD30_2: D30.2 D32.2 | length 51.1
  Top Layer w60: D32.2@3933.25,4397.09 D30.2@3984.31,4397.09
NetD33_1: D33.1 T2.6 | length 433.3
  Top Layer w100: 3715.35,5635.35 3721.81,5641.81 T2.6@3872.13,5641.81
  Bottom Layer w100: D33.1@3710.71,5370 3710.71,5630.71 3720,5640
  other v1: 3695,5615 3740,5615 3695,5655 3740,5655
NetD34_1: D34.1 R52.2 | length 120.3
  Bottom Layer w60: R52.2@2275.08,4499.33 2286.26,4510.51 D34.1@2286.26,4615
NetD36_1: D36.1 R98.2 | length 103.4
  Top Layer w70: 3897.26,4167.26 D36.1@4000.63,4167.26
NetQ1_1: Q1.1 Q2.3 R15.1 | length 1526.2
  Bottom Layer w40: 1105,1028.43 865,788.43 865,280.43 940.04,205.39 Q2.3@1512.72,205.39
NetQ1_2: pad.1@1154.96,505.39 R11.1 R13.2
  other v1: 1635,1345.43 1635,1390.43 1635,1440.43
NetQ3_2: Q3.2 Q3.4 R18.1 R20.2 | length 276.3
  Bottom Layer w40: Q3.2@2453.07,980 Q3.4@2555.43,980 ; R20.2@2625,891.5 2625,980.43
  Bottom Layer w50: 2625,980.43 R18.1@2710,980.43
NetQ4_2: Q4.2 R77.1 | length 307.5
  Top Layer w25: Q4.2@2345.25,241.18 2349.5,245.43 R77.1@2610,245.43 ; R77.1@2606.63,248.81 R77.1@2610,245.43 ; R77.1@2625,230.43 R77.1@2610,245.43 ; R77.1@2625,245.43 R77.1@2610,245.43
NetQ9_1: Q9.1 Q10.3 R49.1 | length 1526.2
  Bottom Layer w40: 1105,4492.99 865,4252.99 865,3745 940.04,3669.96 Q10.3@1512.72,3669.96
NetQ9_2: pad.1@1160,3970 R46.1 R50.2
  other v1: 1635,4810 1635,4855 1635,4905
NetQ12_2: Q12.2 R81.1 | length 423.5
  Bottom Layer w30: Q12.2@2130.16,3852.72 2130.16,3784.84 2150,3765 2477.52,3765 R81.1@2477.56,3764.96
NetQ13_1: Q13.1 Q16.1 R88.2 | length 316
  Bottom Layer w20: Q13.1@4057.6,4432.24 4060,4429.84 4060,4400 4075,4385 4180,4385 Q16.1@4217.4,4347.6
  Bottom Layer w30: R88.2@4190,4260 4220,4290 4220,4346.85 Q16.1@4220.75,4347.6 Q16.1@4217.4,4347.6
NetQ13_3: Q13.3 R58.1 R86.2 | length 478.5
  Bottom Layer w25: R58.1@3988.78,4365 3990,4363.78 4016.02,4337.76 Q13.3@4095,4337.76
  Bottom Layer w50: R86.2@3710.55,4300 3726.89,4300 3751.89,4275 3960,4275 3990,4305 R58.1@3990,4363.78
NetQ19_1: Q19.1 R96.2 | length 104.2
  Bottom Layer w30: R96.2@3298.78,3965 3311.38,3977.6 Q19.1@3397.76,3977.6
NetQ19_2: Q19.2 R59.1 R87.2 | length 214.7
  Top Layer w60: R59.1@3260,4110 R87.2@3355,4110
  Top Layer w70: R87.2@3365,4108.31 3410,4108.31
  Bottom Layer w35: Q19.2@3397.76,4052.4 3415,4069.65 v1(3415,4090) v1@3415,4120
  other v1: 3415,4125
NetQ20_1: Q20.1 R94.2 R97.2 | length 354.4
  Bottom Layer w20: R97.2@3865,4035 3895,4035 3935,4075 3935,4140 3947.56,4152.56 4027.44,4152.56 4052.52,4127.48 Q20.1@4052.52,4102.76
  Bottom Layer w60: 3865,3985 R97.2@3865,4030
NetQ20_3: Q20.3 R86.1 R88.1 | length 687.1
  Bottom Layer w30: 3866.06,4207.2 3860.08,4201.22 4011.14,4201.22 Q20.3@4015.12,4197.24 4017.87,4200 4073,4200 4090,4217 R88.1@4090,4240
  Bottom Layer w50: R86.1@3529.45,4300 3525,4295.55 3525,4235 3558.78,4201.22 3860.08,4201.22
NetR2_1: R2.1 R4.2
NetR3_1: R3.1 R5.2
NetR5_1: R5.1 R7.2
NetR6_1: R6.1 R9.2
NetR7_1: R7.1 R8.2
NetR8_1: R8.1 R10.2
NetR10_1: R10.1 R11.2
NetR13_1: R13.1 R16.2
NetR14_1: R14.1 R15.2
NetR23_1: R23.1 R28.2 | length 75
  Bottom Layer w10: R23.1@2545,570 R23.1@2550,570
  Bottom Layer w60: R28.2@2550,490 R23.1@2550,560
NetR37_1: R37.1 R39.2
NetR38_1: R38.1 R40.2
NetR40_1: R40.1 R42.2
NetR41_1: R41.1 R44.2
NetR42_1: R42.1 R43.2
NetR43_1: R43.1 R45.2
NetR45_1: R45.1 R46.2
NetR48_1: R48.1 R49.2
NetR50_1: R50.1 R51.2
NetR61_1: R61.1 R83.2 U3.1 | length 206.8
  Bottom Layer w50: U3.1@5345.61,3950 5350,3954.39 R83.2@5350,4050 R61.1@5350,4155
NetR74_2: R74.2 R75.2 U3.3 | length 2311.2
  Top Layer w50: R74.2@2803.78,3595 3819.57,3595 3884.57,3660 v1(3935,3660) v1@3960,3660
  Bottom Layer w50: v1(3935,3660) v1(3970,3660) 4220,3660 4410,3850 U3.3@4984.39,3850
RT/CT: C65.1 Q15.1 R60.1 U2.4 | length 798.4
  Top Layer w30: Q15.1@2875.31,3767.36 2910,3802.05 2910,4050 2933.78,4073.78 v1(2933.78,4220) v1(2900,4220)
  Bottom Layer w40: 2890,3995 2885,3995 2878.78,4001.22 R60.1@2878.78,4060 2880.08,4061.3 C65.1@2880.08,4151.22 2880.08,4219.31 2879.39,4220 v1(2900,4220) v1(2933.78,4220)
RT/CT_PSR: C31.1 Q7.1 R26.1 U1.4 | length 736.3
  Top Layer w30: v1(2945,760) 2945,550 2970.87,524.13 3085,524.13 3105.31,503.82 Q7.1@3105.31,482.8
  Top Layer w40: v1(2911.22,760) 2928.11,760 ; 2930,758.11 2928.11,760 ; v1(2945,760) 2928.11,760
  Bottom Layer w25: R26.1@2880,595.43 R26.1@2887.72,587.72
  Bottom Layer w40: 2880,745 2895,760 v1(2911.22,760) v1(2945,760)
  Bottom Layer w50: R26.1@2880,595.43 C31.1@2880,685.43 2880,745 ; 2880.04,530 R26.1@2880.04,587.72
SW_node: D22.2 pad.1@3958.78,5068.66 T2.3 | length 408.6
  Top Layer w60: v1(3720,6260) 3760,6220 v1(3760,6213.31) v1(3760,6173.31) T2.3@3872.13,6173.31
  Bottom Layer w60: D22.2@3720,6196.26 v1(3720,6260) 3760,6220 v1(3760,6213.31) v1(3760,6173.31)
  Bottom Layer w80: D22.2@3713.74,6170 3740,6170
SW_PSR: D6.2 pad.1@3958.78,1594.09 T1.3 | length 452.1
  Top Layer w60: v1@3705,2795.87 v1(3751.22,2749.65) v1(3751.22,2709.65) T1.3@3863.35,2709.65
  Bottom Layer w60: D6.2@3683.74,2710 3705,2731.26 v1(3705,2800) 3751.22,2753.78 v1(3751.22,2749.65) v1(3751.22,2709.65)
  Bottom Layer w80: D6.2@3704.96,2706.34 3731.22,2706.34
VDD: C54.1 C55.1 C56.1 C63.1 D35.1 Q9.3 Q11.3 R51.1 R59.2 U2.7 | length 2702.3
  Top Layer w50: v1@2830,4399.85 v1@2830,4420 ; v1(2830,4430) v1@2830,4420 ; 3095,4400 3075,4420 v1@2830,4420
  Top Layer w60: v1(2150,4355) v1(2192.5,4355) v1(2235,4355) 2325,4445 v1(2495,4445) v1(2540,4445) ; 3095,4400 3095,4110 ; R59.2@3175,4110 3095,4110 ; v1@3210.08,3885 3140,3885 3095,3930 3095,4110
  Bottom Layer w20: D35.1@3505.79,3871.22 D35.1@3515,3862.01
  Bottom Layer w25: v1(2495,4445) 2495,4393.86 Q11.3@2499.06,4389.8 ; U2.7@3102.36,3881.22 3155.91,3881.22 ; C55.1@3260.08,3859.33 3210.08,3859.33 ; C55.1@3275.08,3874.33 C55.1@3268.19,3881.22 ; 3155.91,3881.22 v1@3170.08,3881.22 ; 3155.91,3881.22 v1@3170.08,3895.39 ; v1@3170.08,3881.22 v1@3170.08,3895.39 ; v1@3170.08,3881.22 3170.08,3859.33 3210.08,3859.33 ; v1@3170.08,3881.22 v1@3210.08,3881.22 ; v1@3170.08,3895.39 3210.08,3895.39 ; 3210.08,3859.33 v1@3210.08,3881.22 ; v1@3210.08,3881.22 3210.08,3895.39 ; v1@3210.08,3881.22 C55.1@3268.19,3881.22 ; 3210.08,3895.39 3254.02,3895.39 C55.1@3268.19,3881.22
  Bottom Layer w40: v1(2495,4445) 2517.5,4445 ; 2520,4389.8 2517.5,4392.3 2517.5,4445 ; 2550.2,4389.8 2540,4400 v1(2540,4445) 2517.5,4445
  Bottom Layer w50: 2520,4389.8 2550.2,4389.8 2570,4370 2805,4370 v1(2830,4395) v1(2830,4430) ; C63.1@3375.08,3871.22 D35.1@3505.79,3871.22
  Bottom Layer w60: C55.1@3275.08,3874.33 3371.97,3874.33 C63.1@3375.08,3871.22
  other v1: 3220,3881.22 3175.08,3881.61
